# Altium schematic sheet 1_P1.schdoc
size 568 x 416 mm; Symbol: Drawing-Symbol_A4; Device: Drawing-Symbol_A4; @Project Name: Mini-fc; @Page Count: 1; @Update Date: 2025-06-22; @Create Date: 2025-06-20; @Schematic Name: Schematic1; @Page No: 1; @Page Name: P1; Company: EasyEDA.com; Version: V1.0; Page Size: A4; @Create Time: 02:56:04; @Update Time: 19:26:06; Width: 2200; Height: 1600; Region Start: 1; X Region Count: 6; Y Region Count: 4; Blade Width: 10; Title Block Position: 3; @Board Name: Board1
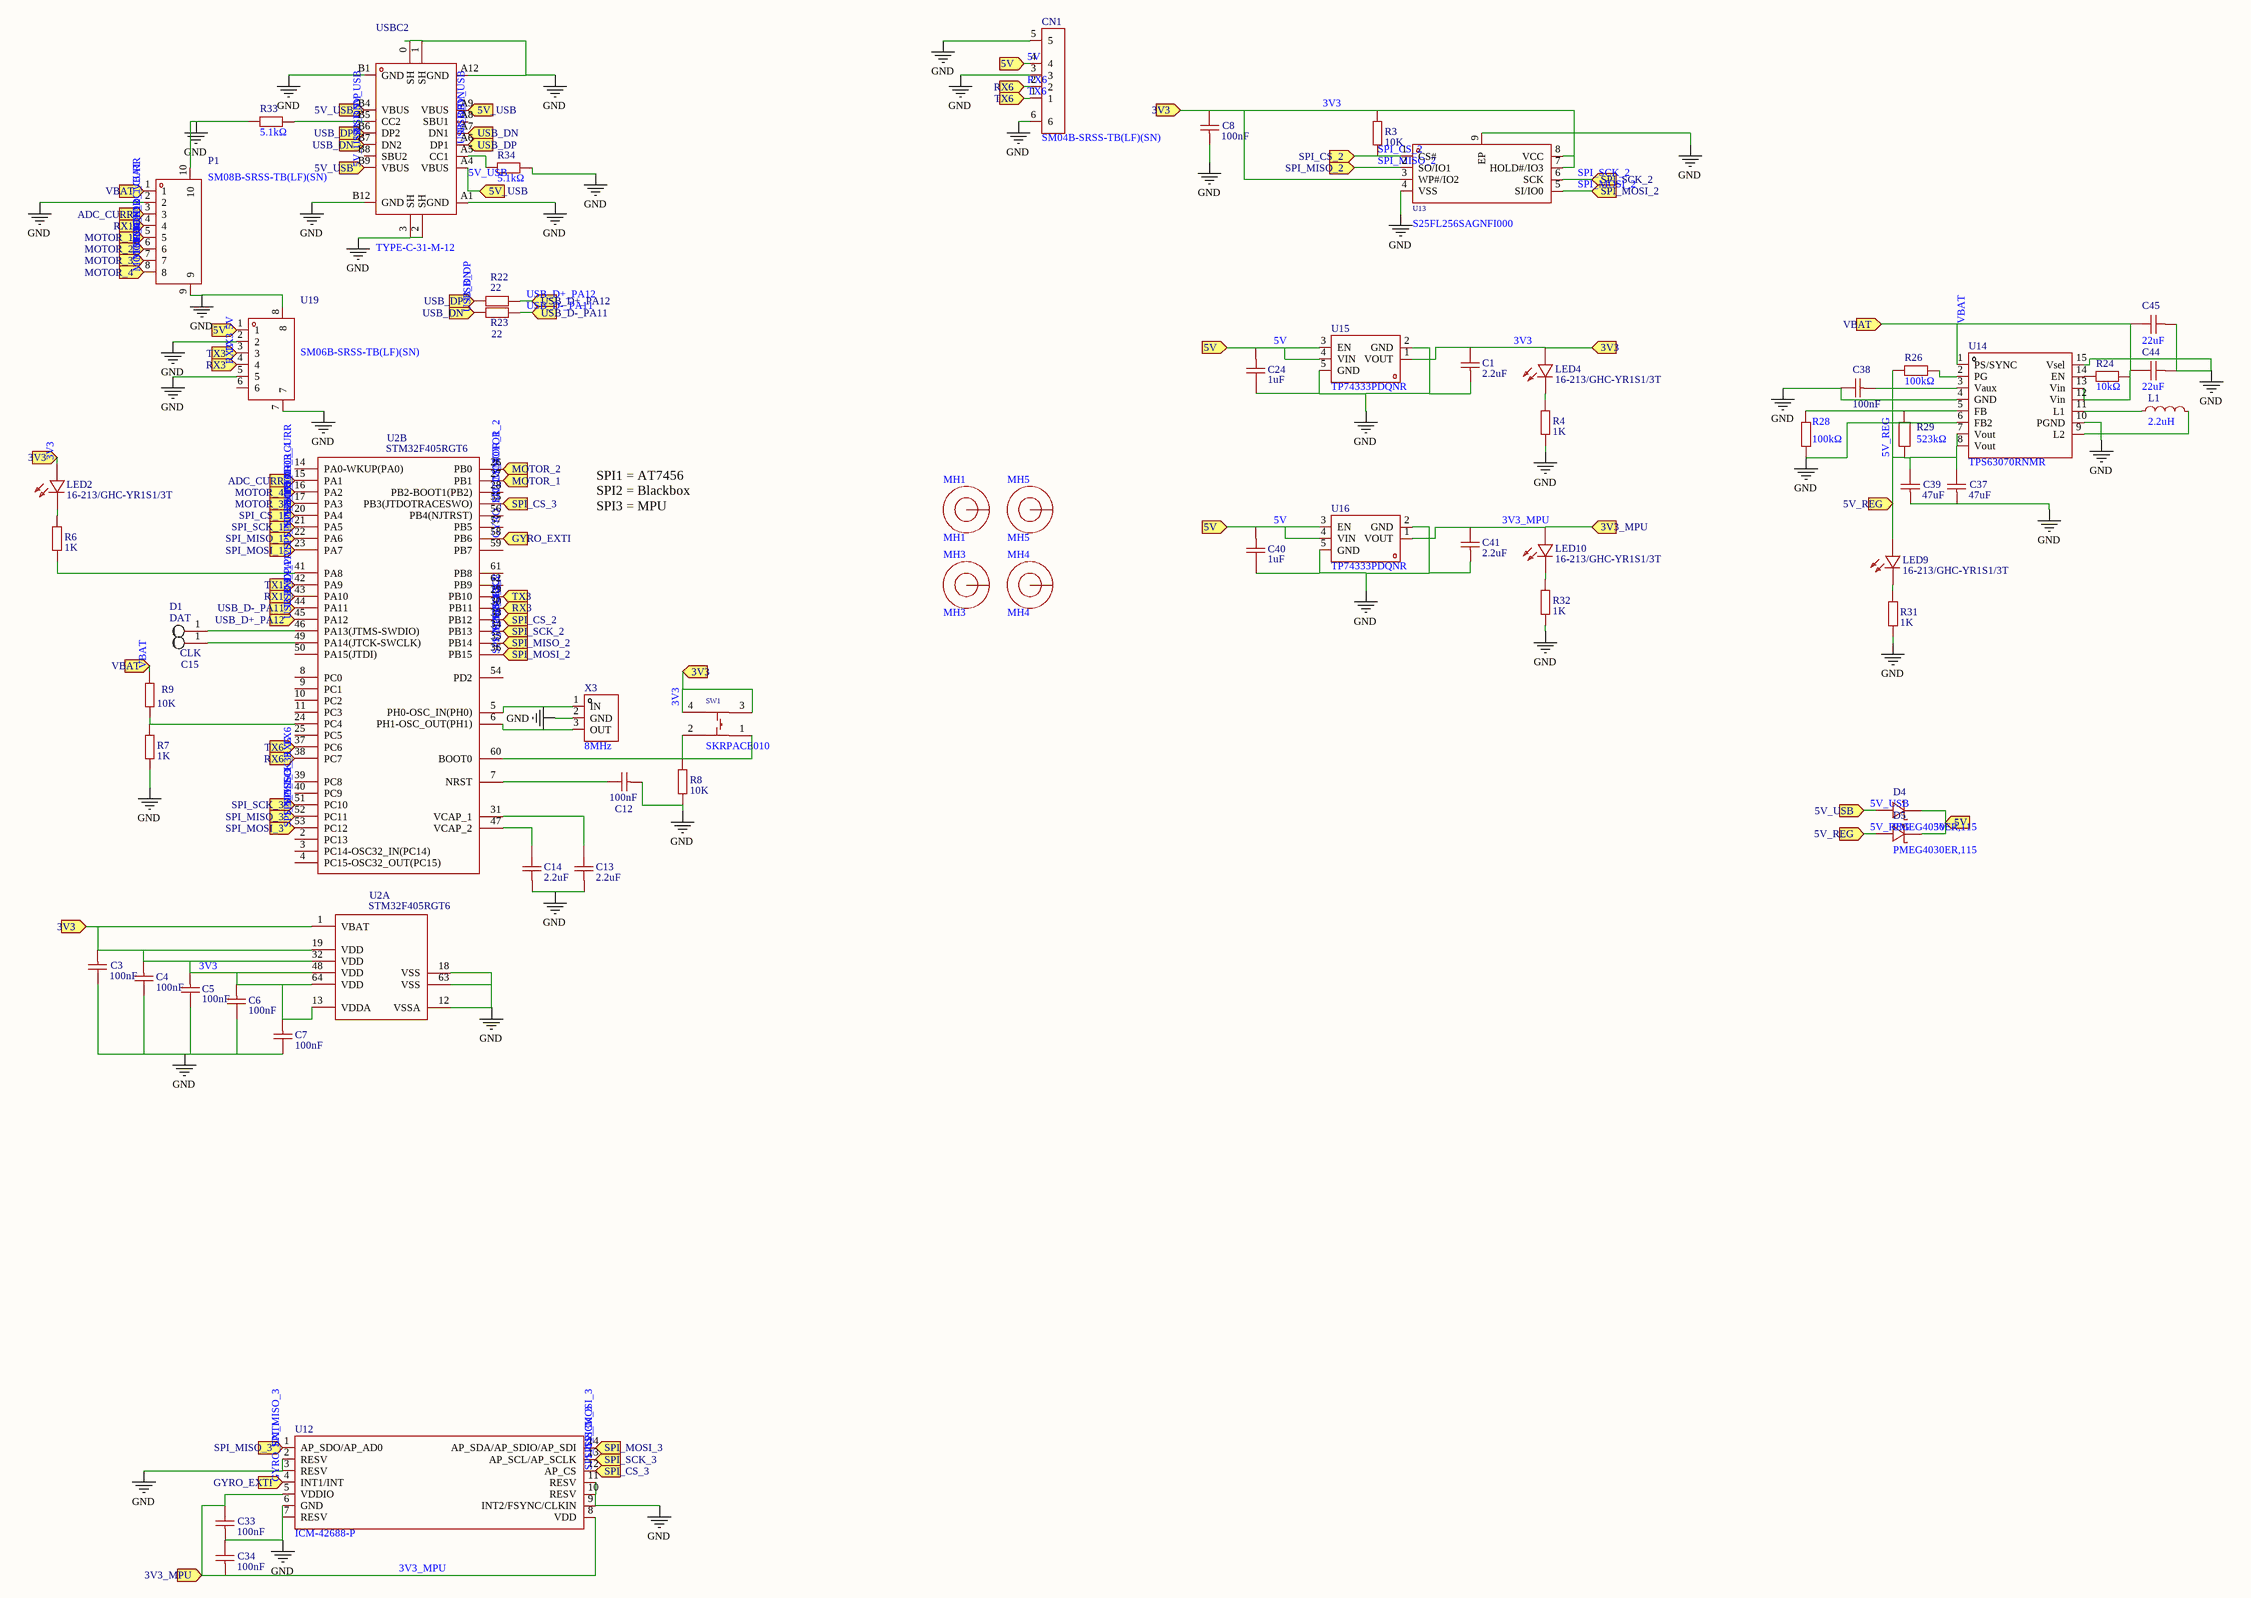
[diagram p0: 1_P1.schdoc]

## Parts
C1  2.2uF  [C0603]
C3  100nF  [C0402]
C4  100nF  [C0402]
C5  100nF  [C0402]
C6  100nF  [C0402]
C7  100nF  [C0402]
C8  100nF  [C0402]
C12  100nF  [C0402]
C13  2.2uF  [C0402]
C14  2.2uF  [C0402]
C15  CLK  [TEST PAD]
C24  1uF  [C0402]
C33  100nF  [C0402]
C34  100nF  [C0402]
C37  47uF  [C0805]
C38  100nF  [C0402]
C39  47uF  [C0805]
C40  1uF  [C0402]
C41  2.2uF  [C0603]
C44  22uF  [C0402]
C45  22uF  [C0402]
CN1  SM04B-SRSS-TB(LF)(SN)  [CONN-SMD_4P-P1.00_SM04B-SRSS-TB-LF-SN]
D1  DAT  [TEST PAD]
D4  PMEG4030ER,115  [SOD-123_L2.6-W1.7-LS3.5-RD]
D5  PMEG4030ER,115  [SOD-123_L2.6-W1.7-LS3.5-RD]
L1  2.2uH  [IND-SMD_L7.1-W6.5-P5.60]
LED2  16-213/GHC-YR1S1/3T  [LED0402-R-RD]
LED4  16-213/GHC-YR1S1/3T  [LED0402-R-RD]
LED9  16-213/GHC-YR1S1/3T  [LED0402-R-RD]
LED10  16-213/GHC-YR1S1/3T  [LED0402-R-RD]
MH1  MH1  [MHOLE-3MM-simple]
MH3  MH3  [MHOLE-3MM-simple]
MH4  MH4  [MHOLE-3MM-simple]
MH5  MH5  [MHOLE-3MM-simple]
P1  SM08B-SRSS-TB(LF)(SN)  [CONN-TH_SM08B-SRSS-TB-LF-SN]
R3  10K  [R0402]
R4  1K  [R0402]
R6  1K  [R0402]
R7  1K  [R0402]
R8  10K  [R0402]
R9  10K  [R0402]
R22  22  [R0402]
R23  22  [R0402]
R24  10kΩ  [R0805]
R26  100kΩ  [R0402]
R28  100kΩ  [R0402]
R29  523kΩ  [R0402]
R31  1K  [R0402]
R32  1K  [R0402]
R33  5.1kΩ  [R0402]
R34  5.1kΩ  [R0402]
SW1  SKRPACE010  [KEY-SMD_4P-L4.2-W3.2-P2.20-LS4.6]
U2  STM32F405RGT6  [LQFP-64_L10.0-W10.0-P0.50-LS12.0-BL]  (parts A,B of 2)
U12  ICM-42688-P  [LGA-14_L3.0-W2.5-P0.50-TL]
U13  S25FL256SAGNFI000  [WSON-8_L8.0-W6.0-P1.27-BL-EP]
U14  TPS63070RNMR  [VQFN-HR-15_L3.0-W2.5-P0.50-BL_TPS63070RNMR]
U15  TP74333PDQNR  [XDFN-4_L1.0-W1.0-P0.65-BL-EP]
U16  TP74333PDQNR  [XDFN-4_L1.0-W1.0-P0.65-BL-EP]
U19  SM06B-SRSS-TB(LF)(SN)  [CONN-SMD_SM06B-SRSS-TB-LF-SN]
USBC2  TYPE-C-31-M-12  [USB-C_SMD-TYPE-C-31-M-12]
X3  8MHz  [OSC-SMD_3P-L3.2-W1.3-P1.20]

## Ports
3V3 (in), 3V3_MPU (in), 5V (in), 5V_REG (in), 5V_USB (in), ADC_CURR (in), GYRO_EXTI (in), MOTOR_1 (in), MOTOR_2 (in), MOTOR_3 (in), MOTOR_4 (in), RX1 (in), RX3 (in), RX6 (in), SPI_CS_1 (in), SPI_CS_2 (in), SPI_CS_3 (in), SPI_MISO_1 (in), SPI_MISO_2 (in), SPI_MISO_3 (in), SPI_MOSI_1 (in), SPI_MOSI_2 (in), SPI_MOSI_3 (in), SPI_SCK_1 (in), SPI_SCK_2 (in), SPI_SCK_3 (in), TX1 (in), TX3 (in), TX6 (in), USB_D+_PA12 (in), USB_D-_PA11 (in), USB_DN (in), USB_DP (in), VBAT (in)

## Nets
GND: C1.1 C3.2 C4.2 C5.2 C6.2 C7.2 C8.1 C12.1 C13.2 C14.2 C24.1 C33.1 C34.2 C37.1 C38.2 C39.1 C40.1 C41.1 C44.2 C45.2 CN1.3 CN1.5 CN1.6 P1.2 P1.9 P1.10 R4.1 R7.1 R8.1 R28.1 R31.1 R32.1 R33.1 R34.2 U2.12(VSSA) U2.18(VSS) U2.63(VSS) U12.2(RESV) U12.3(RESV) U12.6(GND) U12.7(RESV) U12.9(INT2/FSYNC/CLKIN) U12.10(RESV) U12.11(RESV) U13.4(VSS) U13.9(EP) U14.4(GND) U14.6(FB2) U14.10(PGND) U14.15(Vsel) U15.2(GND) U15.5(GND) U16.2(GND) U16.5(GND) U19.2 U19.5 U19.7 U19.8 USBC2.0(SH) USBC2.1(SH) USBC2.2(SH) USBC2.3(SH) USBC2.A1(GND) USBC2.A12(GND) USBC2.B1(GND) USBC2.B12(GND) X3.2(GND)
3V3: C1.2 C3.1 C4.1 C5.1 C6.1 C7.1 C8.2 LED2.1(A) LED4.1(A) R3.2 SW1.3 SW1.4 U2.1(VBAT) U2.13(VDDA) U2.19(VDD) U2.32(VDD) U2.48(VDD) U2.64(VDD) U13.3(WP#/IO2) U13.7(HOLD#/IO3) U13.8(VCC) U15.1(VOUT) ; port 3V3
3V3_MPU: C33.2 C34.1 C41.2 LED10.1(A) U12.5(VDDIO) U12.8(VDD) U16.1(VOUT) ; port 3V3_MPU
5V: C24.2 C40.2 CN1.4 D4.1(K) D5.1(K) U15.3(EN) U15.4(VIN) U16.3(EN) U16.4(VIN) U19.1 ; port 5V
5V_REG: C37.2 C39.2 D5.2(A) LED9.1(A) R26.1 R29.1 U14.7(Vout) U14.8(Vout) ; port 5V_REG
5V_USB: D4.2(A) USBC2.A4(VBUS) USBC2.A9(VBUS) USBC2.B4(VBUS) USBC2.B9(VBUS) ; port 5V_USB
ADC_CURR: P1.3 U2.15(PA1) ; port ADC_CURR
GYRO_EXTI: U2.58(PB6) U12.4(INT1/INT) ; port GYRO_EXTI
MOTOR_1: P1.5 U2.27(PB1) ; port MOTOR_1
MOTOR_2: P1.6 U2.26(PB0) ; port MOTOR_2
MOTOR_3: P1.7 U2.17(PA3) ; port MOTOR_3
MOTOR_4: P1.8 U2.16(PA2) ; port MOTOR_4
RX1: P1.4 U2.43(PA10) ; port RX1
RX3: U2.30(PB11) U19.4 ; port RX3
RX6: CN1.2 U2.38(PC7) ; port RX6
SPI_CS_1: U2.20(PA4) ; port SPI_CS_1
SPI_CS_2: R3.1 U2.33(PB12) U13.1(CS#) ; port SPI_CS_2
SPI_CS_3: U2.55(PB3(JTDOTRACESWO)) U12.12(AP_CS) ; port SPI_CS_3
SPI_MISO_1: U2.22(PA6) ; port SPI_MISO_1
SPI_MISO_2: U2.35(PB14) U13.2(SO/IO1) ; port SPI_MISO_2
SPI_MISO_3: U2.52(PC11) U12.1(AP_SDO/AP_AD0) ; port SPI_MISO_3
SPI_MOSI_1: U2.23(PA7) ; port SPI_MOSI_1
SPI_MOSI_2: U2.36(PB15) U13.5(SI/IO0) ; port SPI_MOSI_2
SPI_MOSI_3: U2.53(PC12) U12.14(AP_SDA/AP_SDIO/AP_SDI) ; port SPI_MOSI_3
SPI_SCK_1: U2.21(PA5) ; port SPI_SCK_1
SPI_SCK_2: U2.34(PB13) U13.6(SCK) ; port SPI_SCK_2
SPI_SCK_3: U2.51(PC10) U12.13(AP_SCL/AP_SCLK) ; port SPI_SCK_3
TX1: U2.42(PA9) ; port TX1
TX3: U2.29(PB10) U19.3 ; port TX3
TX6: CN1.1 U2.37(PC6) ; port TX6
USB_D+_PA12: R22.2 U2.45(PA12) ; port USB_D+_PA12
USB_D-_PA11: R23.2 U2.44(PA11) ; port USB_D-_PA11
USB_DN: R23.1 USBC2.A7(DN1) USBC2.B7(DN2) ; port USB_DN
USB_DP: R22.1 USBC2.A6(DP1) USBC2.B6(DP2) ; port USB_DP
VBAT: C44.1 C45.1 P1.1 R9.2 R24.2 U14.1(PS/SYNC) U14.12(Vin) U14.13(Vin) ; port VBAT
NetC12_2: C12.2 U2.7(NRST)
NetC13_1: C13.1 U2.31(VCAP_1)
NetC14_1: C14.1 U2.47(VCAP_2)
NetC15_1: C15.1 U2.49(PA14(JTCK-SWCLK))
NetC38_1: C38.1 U14.3(Vaux)
NetD1_1: D1.1 U2.46(PA13(JTMS-SWDIO))
NetL1_1: L1.1 U14.11(L1)
NetL1_2: L1.2 U14.9(L2)
NetLED2_2: LED2.2(C) R6.2
NetLED4_2: LED4.2(C) R4.2
NetLED9_2: LED9.2(C) R31.2
NetLED10_2: LED10.2(C) R32.2
NetR6_1: R6.1 U2.41(PA8)
NetR7_2: R7.2 R9.1 U2.24(PC4)
NetR8_2: R8.2 SW1.1 SW1.2 U2.60(BOOT0)
NetR24_1: R24.1 U14.14(EN)
NetR26_2: R26.2 U14.2(PG)
NetR28_2: R28.2 R29.2 U14.5(FB)
NetR33_2: R33.2 USBC2.B5(CC2)
NetR34_1: R34.1 USBC2.A5(CC1)
NetU2_5: U2.5(PH0-OSC_IN(PH0)) X3.1(IN)
NetU2_6: U2.6(PH1-OSC_OUT(PH1)) X3.3(OUT)

Not connected (* = marked no-connect by the designer): MH1 1; MH3 1; MH4 1; MH5 1; U2 2(PC13) 3(PC14-OSC32_IN(PC14)) 4(PC15-OSC32_OUT(PC15)) 8(PC0) 9(PC1) 10(PC2) 11(PC3) 14(PA0-WKUP(PA0)) 25(PC5) 28(PB2-BOOT1(PB2)) 39(PC8) 40(PC9) 50(PA15(JTDI)) 54(PD2) 56(PB4(NJTRST)) 57(PB5) 59(PB7) 61(PB8) 62(PB9); U19 6; USBC2 A8(SBU1) B8(SBU2)

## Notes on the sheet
- SPI1 = AT7456
  SPI2 = Blackbox
  SPI3 = MPU

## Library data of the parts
C1 C41 = CL10A225KO8NNNC: Manufacturer: SAMSUNG; Convert to PCB: yes; nameAlias: Capacitance
C3-C8 C12 C33 C34 C38 = CL05B104KO5NNNC: Manufacturer: SAMSUNG; Convert to PCB: yes; nameAlias: Capacitance
C13 C14 = CL05A225MA5NUNC: Manufacturer: SAMSUNG; Convert to PCB: yes; nameAlias: Capacitance; Contributor: LCSC
C15 = CLK: Convert to PCB: yes; Contributor: Brich
C24 C40 = CL05A105KA5NQNC: Manufacturer: SAMSUNG; Convert to PCB: yes; nameAlias: Capacitance
C37 C39 = CL21A476MQYNNNE: Manufacturer: SAMSUNG; Convert to PCB: yes; nameAlias: Capacitance
C44 C45 = GRM158R61A226ME15D: Manufacturer: muRata(村田); Add into BOM: yes; Tolerance: ±20%
CN1 = SM04B-SRSS-TB(LF)(SN): Manufacturer: JST; Add into BOM: yes; Pins Structure: 1x4P; Pitch: 1mm; Reference Series: SH; Number of PINs Per Row: 4; Current Rating (Max): 1A; Rated Voltage (Max): 50V; Plastic Material: PA; Flame Retardant Rating: UL94V-0; Supplementary Features: Auxiliary soldering legs; Z-Height of the Board: 2.9mm; X-Length of Bottom Edge on Board (Spacing Line): 6mm; Y-Width of Bottom Edge on Board: 4.32mm
D1 = DAT: Convert to PCB: yes; Contributor: Brich
D4 D5 = PMEG4030ER,115: Manufacturer: Nexperia(安世); Add into BOM: yes; Forward Voltage (Vf@If): 540mV@3A; Reverse Voltage (Vr): 40V; Average Rectified Current (Io): 3A; Reverse Leakage Current (Ir): 100uA@40V
L1 = SPM6530T-2R2M: Manufacturer: TDK; Add into BOM: yes; Tolerance: ±20%; Saturation Current (Isat): 8.4A
LED2 LED4 LED9 LED10 = 16-213/GHC-YR1S1/3T: Manufacturer: EVERLIGHT; Convert to PCB: yes
MH1 MH3-MH5 = MHOLE-3MM-simple: Add into BOM: no; Convert to PCB: yes
P1 = SM08B-SRSS-TB(LF)(SN): Manufacturer: JST; Add into BOM: yes; Pins Structure: 1x8P; Pitch: 1mm; Reference Series: SH; Number of PINs Per Row: 8; Current Rating (Max): 1A; Rated Voltage (Max): 50V; Plastic Material: PA; Flame Retardant Rating: UL94V-0; Supplementary Features: 辅助焊脚; Z-Height of the Board: 2.9mm; X-Length of Bottom Edge on Board (Spacing Line): 10mm; Y-Width of Bottom Edge on Board: 4.32mm
R3 R8 R9 = 0402WGF1002TCE: Manufacturer: UniOhm; Convert to PCB: yes; nameAlias: Resistance (Ohms)
R4 R6 R7 R31 R32 = 0402WGF1001TCE: Manufacturer: UniOhm; Convert to PCB: yes; nameAlias: Resistance (Ohms)
R22 R23 = 0402WGF220JTCE: Manufacturer: UniOhm; Convert to PCB: yes; nameAlias: Resistance (Ohms)
R24 = RC0805FR-0710KL: Manufacturer: YAGEO(国巨); Add into BOM: yes; Tolerance: ±1%; Temperature Coefficient: ±100ppm/℃
R26 R28 = RC0402FR-07100KL: Manufacturer: YAGEO(国巨); Add into BOM: yes; Tolerance: ±1%; Temperature Coefficient: ±100ppm/℃
R29 = CRCW0402523KFKED: Manufacturer: VISHAY(威世); Add into BOM: yes; Tolerance: ±1%; Temperature Coefficient: ±100ppm/℃
R33 R34 = RC0402FR-075K1L: Manufacturer: YAGEO(国巨); Add into BOM: yes; Tolerance: ±1%; Power(Watts): 62.5mW; Voltage-Supply(Max): 50V; Temperature Coefficient: ±100ppm/℃
SW1 = SKRPACE010: Manufacturer: ALPSALPINE(阿尔卑斯阿尔派); Add into BOM: yes; Circuit: SPST; Actuator Style: Oval button; Switch Length: 4.2mm; Switch Width: 3.2mm; Switch Height: 2.5mm; Contact Current: 50mA; Voltage Rating (DC): 16V
U2 = STM32F405RGT6: Manufacturer: ST; subpart_no: 1; tags: STM32; Convert to PCB: yes
U12 = ICM-42688-P: Manufacturer: TDK InvenSense(应美盛); Add into BOM: yes; Sensor Type: Accelerometer gyroscope
U13 = S25FL256SAGNFI000_C914933: Manufacturer: CYPRESS(赛普拉斯); Add into BOM: yes
U14 = TPS63070RNMR: Manufacturer: TI(德州仪器); Add into BOM: yes; Function: Boost type; Output Type: Adjustable; Voltage - Supply: 2V~16V; Output Voltage: 2.5V~9V; Frequency - Switching: 2.4MHz; Number of Outputs: 1; Topology: Step-down-Boost; Switch tube (built-in/external): Built-in
U15 U16 = TP74333PDQNR: Manufacturer: TECH PUBLIC(台舟); Add into BOM: yes
U19 = SM06B-SRSS-TB(LF)(SN): Manufacturer: JST; Add into BOM: yes; Pins Structure: 1x6P; Pitch: 1mm; Reference Series: SH; Number of PINs Per Row: 6; Current Rating (Max): 1A; Rated Voltage (Max): 50V; Plastic Material: PA; Flame Retardant Rating: UL94V-0; Supplementary Features: 辅助焊脚; Z-Height of the Board: 2.9mm; X-Length of Bottom Edge on Board (Spacing Line): 8mm; Y-Width of Bottom Edge on Board: 4.32mm
USBC2 = TYPE-C-31-M-12: Manufacturer: 韩国韩荣; Add into BOM: yes; Connector Type: Type-C; Gender: Female; Number of Contacts: 16P; Number of Ports: 1; Current Rating - Power (Max): 5A
X3 = CSTNE8M00G520000R0: Manufacturer: muRata(村田); Add into BOM: yes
